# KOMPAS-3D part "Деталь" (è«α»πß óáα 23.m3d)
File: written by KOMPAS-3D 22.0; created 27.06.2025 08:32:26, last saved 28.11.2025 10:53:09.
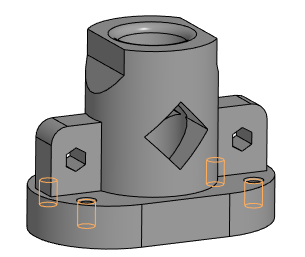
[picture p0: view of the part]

Document properties: Автор: alymovy@yandex.ru; Организация: HP; Полное имя файла: Корпус вар 23.cdw

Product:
- Part/product: Деталь
    Материал: Полиамид П-12Б-20 ТУ 6-05-898-73 (density 1020 kg/m3)
    Масса: 0.534283
    Форматы листов документа: A3

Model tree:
1. Эскиз:1
2. Элемент выдавливания:1
     Расстояние 1 = 25
3. Эскиз:2  (with: Элемент выдавливания:1)
4. Элемент выдавливания:2
     Расстояние 1 = 85
5. Эскиз:3  (with: Элемент выдавливания:1)
6. Эскиз:4  (with: Элемент выдавливания:2, Элемент выдавливания:1)
7. Элемент выдавливания:3
     Расстояние 1 = 45
8. Эскиз:5  (with: Элемент выдавливания:2)
9. Элемент выдавливания:4
     Расстояние 2 = 80
10. Скругление:1  (with: Элемент выдавливания:4)
     Радиус = 5
11. Эскиз:6  (with: Элемент выдавливания:4)
12. Элемент выдавливания:5
     Расстояние 2 = 30
13. Эскиз:8  (with: Элемент выдавливания:1)
14. Ребро жесткости:2
     Толщина стенки 1 = 20; Толщина стенки 2 = 1
15. Зеркальный массив:4
16. Экземпляр ( 1 )
17. Экземпляр ( 2 )  (with: Ребро жесткости:2)
18. Эскиз:9  (with: Ребро жесткости:2)
19. Элемент выдавливания:7
20. Отверстие:2  (with: Элемент выдавливания:1, Ребро жесткости:2)  (labels: M10)
     Глубина выреза = 20; Диаметр отверстия = 8.3762; Угол конуса дна = 118; Расстояние 1 = 20.2513; Расстояние 2 = 119.749; Диаметр зенковки = 11.5762; Глубина зенковки = 1.6; Угол зенковки = 90
21. M10  (labels: cil0_24705-2004 coarse)
     Длина резьбы = 15; Шаг резьбы = 1.5; Номинальный диаметр резьбы = 10
22. Зеркальный массив:5  (with: Экземпляр ( 1 ), Экземпляр ( 2 ), Отверстие:2)
23. Зеркальный массив:6  (with: Экземпляр ( 1 ), Экземпляр ( 2 ), Зеркальный массив:5, Отверстие:2)
24. Экземпляр ( 2 )  (with: Отверстие:2)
